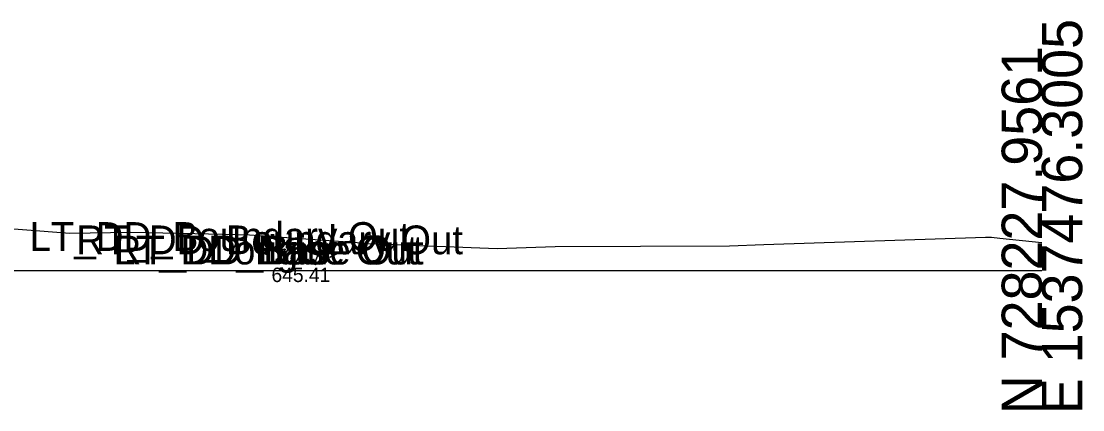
# Model space of a CAD drawing. Extents: x -26 to 1203, y -10 to 9522.
# Drawn here: x 129 to 202.8, y 5990.3 to 6017.3 of the extents above; entities that cross this region are included whole.
import ezdxf

# ---------------------------------------------------------------- set-up
doc = ezdxf.new("R2010")
doc.units = 0
for name, color, linetype in [('Exist Cross Section Cell', 7, 'Continuous'), ('Exist XS Ground Line', 7, 'Continuous'), ('Old_Level_63', 7, 'Continuous'), ('Prop CMT Ditch DDE', 7, 'Continuous'), ('Prop XS Ditch Slope Text', 7, 'Continuous'), ('Prop XS Ditch Standard Text', 7, 'Continuous')]:
    doc.layers.add(name, color=color, linetype=linetype)

msp = doc.modelspace()

# ---------------------------------------------------------------- linework, layer by layer
at = {"layer": 'Exist Cross Section Cell'}
msp.add_line((100, 6000), (200, 6000), dxfattribs=at)
at = {"layer": 'Exist XS Ground Line'}
msp.add_lwpolyline([(126.087, 6003.073), (132.398, 6002.578), (136.631, 6002.659), (141.08, 6002.563), (144.888, 6002.47), (152.387, 6001.94), (153.013, 6001.876), (153.815, 6001.848), (154.336, 6001.832), (162.113, 6001.53), (166.142, 6001.653), (172.085, 6001.687), (178.264, 6001.711), (180.669, 6001.79), (196.065, 6002.31), (196.486, 6002.316), (197.064, 6002.244), (200, 6001.932)], dxfattribs=at)
at = {"layer": 'Prop CMT Ditch DDE'}
for points in [[(148.4, 6001.414), (146.518, 6002.355)], [(148.4, 6001.414), (149.815, 6002.122)], [(148.4, 6001.414), (148.4, 6001.414)]]:
    msp.add_lwpolyline(points, dxfattribs=at)

# ---------------------------------------------------------------- texts
at = {"layer": 'Exist Cross Section Cell'}
for s, p in [('E 1537476.3005', (202.8, 5990)), ('N 728227.9561', (200, 5990))]:
    msp.add_text(s, height=2.8, rotation=90, dxfattribs=at).set_placement(p)
at = {"layer": 'Old_Level_63'}
for s, p in [('LT_DD_Boundary Out', (129.589, 6001.355)), ('RT_DD_Boundary Out', (132.839, 6001.122)), ('RT_DD_Base Out', (135.439, 6000.414)), ('LT_DD_Base Out', (135.487, 6000.414)), ('origin', (143.817, 6000.414))]:
    msp.add_text(s, height=2, dxfattribs=at).set_placement(p)
at = {"layer": 'Prop XS Ditch Slope Text'}
for rotation, p in [(333.43495, (145.598, 6001.29)), (26.56505, (149.397, 6000.31))]:
    msp.add_text('2:1', height=1, rotation=rotation, dxfattribs=at).set_placement(p)
at = {"layer": 'Prop XS Ditch Standard Text'}
msp.add_text('645.41', height=1, dxfattribs=at).set_placement((146.42, 5999.19))

doc.saveas('drawing.dxf')
